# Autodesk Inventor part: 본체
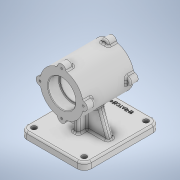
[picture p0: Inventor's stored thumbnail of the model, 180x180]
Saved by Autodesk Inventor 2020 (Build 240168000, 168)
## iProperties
Created: 2022-11
Part Number: 본체
Material: 일반
Document SubType Name: Modeling
Designer: owner
Density: 1 g/cm^3
Appearance: 기본값
Mass: 450.145 g
Surface Area: 796.917 cm^2
Volume: 450.145 cm^3
Author: owner
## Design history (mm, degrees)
sketch "스케치1"
  geometry: C1 r 37 at (0, 0); 1 further point
  constraints: 1 centre point, 1 coincident
  dimensions: "d0" = 74 diameter of C1
extrude "돌출1" new body sketch "스케치1" stored distance "d1" = 87; taper "d2" = 0 deg
node "작업 평면1"
sketch "스케치2"
  geometry: L1 (-37, -43.5)-(37, -43.5) reference; L2 (37, 43.5)-(-37, 43.5) reference; L3 (37, -43.5)-(37, 43.5) reference; L4 (-37, -43.5)-(-37, 43.5) reference; L5 (-55, -70)-(55, -70); L6 (55, -70)-(55, 60); L7 (55, 60)-(-55, 60); L8 (-55, 60)-(-55, -70); 3 further points
  constraints: 8 end point, 2 midpoint, 2 parallel, 1 horizontal, 1 perpendicular, 1 vertical alignment
  dimensions: "d4" = 110 distance of L5.start L5.end; "d5" = 130 distance of L7.end L5.start; "d6" = 70 distance of point (0, 0) point (0, -70)
extrude "돌출2" join sketch "스케치2" distance "d7" = 12; taper "d8" = 0 deg
sketch "스케치3"
  geometry: L1 (-55, -82)-(55, -82) reference; L2 (55, -82)-(55, -70) reference; L3 (-55, -70)-(55, -70) reference; L4 (-55, -82)-(-55, -70) reference; L5 (55, -70)-(-55, -70) reference; L6 (-41, -70)-(-25.336, -26.964); L7 (41, -70)-(25.336, -26.964); A1 r 37 centre (0, 0) between (-25.336, -26.964) and (25.336, -26.964) reference; 3 further points
  constraints: 4 end point, 2 point on circle, 2 point on line
  dimensions: "d9" = 110 deg angle of L3 L6; "d10" = 110 deg angle of L3 L7; "d11" = 14 distance of L6.start L3.start; "d12" = 14 distance of L2.end L7.start
extrude "돌출3" join sketch "스케치3" stored distance "d13" = 10; taper "d14" = 0 deg
sketch "스케치4"
  geometry: L1 (-82, 60)-(-82, -70) reference; L2 (-82, -70)-(-70, -70) reference; L3 (-70, 60)-(-70, -70) reference; L4 (-82, 60)-(-70, 60) reference; L5 (-26.964, 5)-(-26.964, -5) reference; L6 (-70, 5)-(-26.964, 5) reference; L7 (-70, -5)-(-70, 5) reference; L8 (-26.964, -5)-(-70, -5) reference; L9 (-70, -70)-(-70, 60) reference; L10 (-70, 20)-(-44.545, 20); 2 further points
  constraints: 2 end point, 2 point on line, 1 perpendicular
  dimensions: "d15" = 20 distance of point (-70, 0) L10.start
feature "리브1" sketch "스케치4" dims "d16" = 1, "d17" = 10, "d18" = 0, "d19" = 0, "d20" = 1, "d21" = 1
sketch "스케치5"
  geometry: C1 r 37 at (0, 0) reference; 2 further points
  constraints: 1 coincident
hole "구멍1" sketch "스케치5" at (0, 0) diameter "d22" = 42; stored, may be unused: countersink angle "d26" = 90 deg, drill point angle "d28" = 118 deg; dims "d23" = 8, "d24" = 47, "d25" = 19, "d27" = 10
sketch "스케치6"
  geometry: 1 further point
hole "구멍2" sketch "스케치6" at (0, 0) diameter "d29" = 47; stored, may be unused: countersink angle "d33" = 90 deg, drill point angle "d35" = 0 deg; dims "d30" = 8, "d31" = 47, "d32" = 19, "d34" = 19
sketch "스케치7"
  geometry: C1 r 7 at (0, 37); 2 further points
  constraints: 2 vertical alignment, 1 centre point, 1 other
  dimensions: "d36" = 14 diameter of C1
extrude "돌출4" join sketch "스케치7" distance "d37" = 14; taper "d38" = 0 deg
sketch "스케치8"
  geometry: A1 r 7 centre (0, 37) between (6.969, 36.338) and (-6.969, 36.338) reference; 2 further points
  constraints: 1 coincident
hole "구멍3" sketch "스케치8" at (0, 37) diameter "d39" = 3.242; stored, may be unused: countersink angle "d43" = 90 deg, drill point angle "d45" = 118 deg; dims "d40" = 8, "d41" = 47, "d42" = 19, "d44" = 10
sketch "스케치9"
  geometry: C1 r 7 at (0, 37); 2 further points
  constraints: 2 vertical alignment, 1 centre point, 1 other
  dimensions: "d49" = 14 diameter of C1
extrude "돌출5" join sketch "스케치9" distance "d50" = 14; taper "d51" = 0 deg
sketch "스케치10"
  geometry: A1 r 7 centre (0, 37) between (6.969, 36.338) and (-6.969, 36.338) reference; 2 further points
  constraints: 1 coincident
hole "구멍4" sketch "스케치10" at (0, 37) diameter "d52" = 3.242; stored, may be unused: countersink angle "d56" = 90 deg, drill point angle "d58" = 118 deg; dims "d53" = 8, "d54" = 47, "d55" = 19, "d57" = 10
fillet "모깎기1" dims "d62" = 3
fillet "모깎기2" dims "d63" = 3
fillet "모깎기3" dims "d64" = 3
fillet "모깎기4" dims "d65" = 3
fillet "모깎기5" dims "d66" = 3
fillet "모깎기6" dims "d67" = 3
fillet "모깎기7" dims "d68" = 3
fillet "모깎기8" dims "d69" = 3
fillet "모깎기9" dims "d70" = 3
fillet "모깎기10" dims "d71" = 3
fillet "모깎기11" dims "d72" = 3
fillet "모깎기12" dims "d73" = 3
fillet "모깎기13" dims "d74" = 3
fillet "모깎기14" dims "d75" = 3
fillet "모깎기15" dims "d76" = 3
fillet "모깎기16" dims "d77" = 3
fillet "모깎기17" dims "d78" = 12
sketch "스케치11"
  geometry: A1 r 12 centre (-43, -48) between (-55, -48) and (-43, -60) reference; A2 r 12 centre (-43, 58) between (-43, 70) and (-55, 58) reference; A3 r 12 centre (43, 58) between (55, 58) and (43, 70) reference; A4 r 12 centre (43, -48) between (43, -60) and (55, -48) reference; 5 further points
  constraints: 4 coincident
hole "구멍5" sketch "스케치11" at (-43, -48), (-43, 58), (43, 58), (43, -48) diameter "d79" = 9; stored, may be unused: countersink angle "d83" = 90 deg, drill point angle "d85" = 118 deg; dims "d80" = 8, "d81" = 47, "d82" = 19, "d84" = 10
fillet "모깎기18" dims "d86" = 3
fillet "모깎기19" dims "d87" = 3
fillet "모깎기20" dims "d88" = 3
chamfer "모따기1" distance "d89" = 1; stored, may be unused: second distance "d90" = 2, angle "d91" = 45 deg
fillet "모깎기21" dims "d92" = 1
sketch "스케치12"
  geometry: L1 (43, 70)-(-43, 70) reference; 2 further points
  constraints: 1 vertical alignment, 1 other
  dimensions: "d93" = 12 distance from line of point (0, 58) L1
feature "엠보싱1" sketch "스케치12" dims "d94" = 0.5, "d95" = 0
node "솔리드1"
mirror "미러1"
pattern_circular "원형 패턴1" dims angle "d47" = 360 deg
pattern_circular "원형 패턴2" dims angle "d60" = 360 deg
node "투영된 루프1"
node "투영된 루프2"
node "투영된 루프3"
node "투영된 루프4"
node "투영된 루프5"
feature "A9D066F2-1C7D-4E18-AEED-F7BC21143FA4" dims "d22" = 42, "d23" = 8, "d24" = 47, "d25" = 19, "d26" = 90 deg, "d27" = 10, "d28" = 118 deg
other parameters: "d3" = -82
